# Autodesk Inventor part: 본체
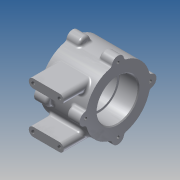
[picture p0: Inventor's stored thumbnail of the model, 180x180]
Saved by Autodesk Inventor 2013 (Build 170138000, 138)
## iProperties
Created: 2015-03
Part Number: 본체
Material: 알루미늄 6061
Document SubType Name: Modeling
Designer: kb543
Density: 2.71 g/cm^3
Mass: 451.224 g
Surface Area: 335.777 cm^2
Volume: 166.503 cm^3
Author: kb543
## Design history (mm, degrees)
sketch "스케치1"
  geometry: L1 (-40, 0)-(40, 0); L2 (-26, 0)-(-26, 37); L3 (-26, 37)-(26, 37); L4 (26, 37)-(26, 0); L5 (-26, 23.5)-(-4, 23.5); L6 (-4, 23.5)-(-4, 21); L7 (-4, 21)-(4, 21); L8 (4, 21)-(4, 23.5); L9 (4, 23.5)-(26, 23.5); 4 further points
  constraints: 18 end point, 6 perpendicular, 4 point on line, 3 midpoint, 2 parallel, 2 vertical alignment, 1 coincident, 1 horizontal
  dimensions: "d0" = 80 distance of L1.start L1.end; "d2" = 74 diameter of L3 L1; "d3" = 52 distance of L2.end L3.end; "d4" = 22 distance of L5.start L5.end; "d5" = 47 diameter of L5 L1; "d6" = 47 diameter of L9 L1; "d7" = 42 diameter of L7 L1
revolve "회전1" sketch "스케치1" stored, may be unused: angle "d8" = 90 deg
sketch "스케치2"
  geometry: C1 r 7 at (0, 37); 2 further points
  constraints: 1 centre point, 1 coincident, 1 vertical alignment, 1 other
  dimensions: "d9" = 7 radius of C1
extrude "돌출1" join sketch "스케치2" distance "d11" = 15; taper "d12" = 0 deg
hole "구멍1" sketch "스케치2" diameter "d13" = 3.242; stored, may be unused: countersink angle "d17" = 90 deg, drill point angle "d19" = 118 deg; dims "d14" = 8, "d15" = 4, "d16" = 2, "d18" = 11
node "작업 평면2"
sketch "스케치3"
  geometry: L1 (15, 19)-(-15, 19); L2 (-15, 19)-(-15, 29); L3 (-15, 29)-(15, 29); L4 (15, 29)-(15, 19); L5 (-36.4, 0)-(36.4, 0) reference; L6 (15, -19)-(-15, -19); L7 (-15, -19)-(-15, -29); L8 (-15, -29)-(15, -29); L9 (15, -29)-(15, -19); A1 r 5 centre (15, 24) between (15, 19) and (15, 29); A2 r 5 centre (-15, 24) between (-15, 29) and (-15, 19); A3 r 5 centre (15, -24) between (15, -29) and (15, -19); A4 r 5 centre (-15, -24) between (-15, -19) and (-15, -29); 3 further points
  constraints: 16 end point, 8 point on circle, 7 symmetric about line, 4 centre point, 3 midpoint, 2 parallel, 1 horizontal, 1 perpendicular, 1 vertical alignment, 2 other
  dimensions: "d25" = 10 distance of L3.end L1.start; "d31" = 30 distance between parallel lines of L2 L4; "d32" = 48 distance of A2.centre A4.centre
extrude "돌출2" join sketch "스케치3" stored distance "d33" = 10; taper "d34" = 0 deg
sketch "스케치4"
  geometry: A1 r 5 centre (15, -24) between (15, -29) and (15, -19) reference; A2 r 5 centre (-15, -24) between (-15, -19) and (-15, -29) reference; A3 r 5 centre (15, 24) between (15, 19) and (15, 29) reference; A4 r 5 centre (-15, 24) between (-15, 29) and (-15, 19) reference; 5 further points
  constraints: 4 coincident
hole "구멍2" sketch "스케치4" at (-15, 24), (15, 24), (15, -24), (-15, -24) diameter "d35" = 4.134; stored, may be unused: countersink angle "d39" = 90 deg, drill point angle "d41" = 118 deg; dims "d36" = 6, "d37" = 4, "d38" = 2, "d40" = 8
node "작업 평면6"
  node "작업 평면5"
sketch "스케치5"
  geometry: L1 (-26, 20.767)-(-26, -20.767) reference; L2 (0, -103.994)-(0, 89.929) reference; 3 further points
  constraints: 2 coincident, 1 vertical alignment, 1 other
  dimensions: "d52" = 26 distance from line of L1 point (0, 0) (derived)
feature "엠보싱1" sketch "스케치5" dims "d0" = 80, "d2" = 74, "d3" = 52, "d4" = 22, "d5" = 47, "d6" = 47, "d7" = 42, "d45" = 0.5, "d46" = 0
fillet "모깎기1" dims "d47" = 0.3
fillet "모깎기2" dims "d48" = 3
fillet "모깎기3" dims "d49" = 3
fillet "모깎기4" dims "d50" = 3
fillet "모깎기5" dims "d51" = 3
chamfer "모따기1" distance "d53" = 1; stored, may be unused: second distance "d54" = 2, angle "d55" = 45 deg
node "솔리드1"
pattern_circular "원형 패턴1" dims angle "d21" = 360 deg
mirror "대칭1"
node "작업 평면3"
other parameters: "d24" = -56, "d42" = -45 deg, "d44" = 0.5
